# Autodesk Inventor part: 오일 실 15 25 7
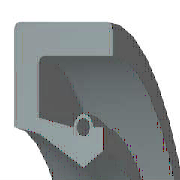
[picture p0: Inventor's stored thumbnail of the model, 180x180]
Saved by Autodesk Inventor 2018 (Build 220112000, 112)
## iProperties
IsCustomPart: 1
Created: 2012-02
Part Number: 오일 실 15 25 7
Material: 고무
Description: 오일 실 - 스프링 장착, 금속 케이스 SM
Document SubType Name: Modeling
Standard: JIS B 2402
Designer: mdu-01
Standards Organization: JIS
Language: ko-KR
Size Designation: 15 25 7 A
Categories: <MemberInstance><Categories><Category DisplayName="샤프트 부품" InternalName="7f7aeb1f-a693-4053-b835-cee3144e0d98" Mnemonic="SHFT"><Category DisplayName="실링" Intern
Density: 0.93 g/cm^3
Appearance: Rubber-Black
Author: mdu-01
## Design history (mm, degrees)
body "Solid1"
revolve "회전1" stored, may be unused: angle "d33" = 360 deg
fillet "모깎기1" dims "d34" = 0.35 (= 0.05 x b)
chamfer "모따기1" distance "d35" = 0.7 (= 0.1 x b); stored, may be unused: second distance "d36" = 0.35 (= 0.05 x b), angle "d41" = 45 deg
sketch "스케치2"
  geometry: L1 (8.714, -5.158)-(9.184, -7); L2 (8.214, -4.55)-(8.714, -5.158); L3 (7.5, -1.75)-(8.214, -4.55); L4 (8.167, -0.875)-(7.5, -1.75); L5 (9.284, -0.875)-(8.167, -0.875); L6 (9.284, -1.575)-(9.284, -0.875); L7 (9.284, -5.25)-(9.284, -2.975); L8 (10.5, -5.25)-(9.284, -5.25); L9 (11.5, -1.75)-(10.5, -5.25); L10 (11.5, 0)-(11.5, -1.75); L11 (12.5, 0)-(11.5, 0); L12 (12.5, -7)-(12.5, 0); L13 (9.184, -7)-(12.5, -7); L14 (0, -9.6)-(0, 1.6) reference; L15 (28, 0)-(14, 0) reference; A1 r 0.7 centre (9.284, -2.275) between (9.284, -2.975) and (9.284, -1.575)
  constraints: 26 end point, 4 horizontal, 4 vertical, 2 point on circle, 1 centre point, 1 collinear, 1 parallel
  dimensions: "d2" = 7 distance of L12.start L11.start (= b); "d4" = 0.875 vertical distance of L10.start L5.start (= 0.125 x b); "d6" = 1 distance of L11.start L10.start (= 0.1 x dd - 0.1 x Diam); "d8" = 1.75 distance of L10.start L9.start (= 0.25 x b); "d10" = 1.75 vertical distance of L8.start L1.end (= 0.25 x b); "d12" = 1 horizontal distance of L9.start L8.start (= 0.1 x dd - 0.1 x Diam); "d14" = 0.7 radius of A1 (= 0.1 x b); "d16" = 0 horizontal distance of A1.centre L7.end; "d18" = 0.7 distance of L6.start L5.start (= 0.1 x b); "d20" = 0.66667 horizontal distance of L4.start L3.start (= 0.0666667 x dd - 0.0666667 x Diam); "d22" = 0.1 horizontal distance of L7.start L1.end (= 0.01 x dd - 0.01 x Diam); "d24" = 0.875 vertical distance of L4.start L3.start (= 0.125 x b); "d26" = 2.8 vertical distance of L3.start L2.start (= 0.4 x b); "d28" = 0.71429 horizontal distance of L3.start L2.start (= 0.0714286 x dd - 0.0714286 x Diam); "d30" = 1.84211 vertical distance of L1.start L1.end (= 0.263158 x b); "d32" = 0.5 horizontal distance of L2.start L1.start (= 0.05 x dd - 0.05 x Diam); "d37" = 0 distance between parallel lines of L15 L11; "d38" = 12.5 distance between parallel lines of L14 L12 (= 0.5 x dd); "d39" = 7.5 distance from line of L14 L3.start (= 0.5 x Diam)
other parameters: "dd" = 25 [user parameter; used in 7 equation terms], "Diam" = 15 [user parameter; used in 7 equation terms], "b" = 7 [user parameter; used in 12 equation terms], "d1" = 8 (derived), "d3" = 1 (derived), "d5" = 2 (derived), "d7" = 2 (derived), "d9" = 2 (derived), "d11" = 2 (derived), "d13" = 0.8 (derived), "d15" = 0 (derived), "d17" = 0.8 (derived), "d19" = 1.33333 (derived), "d21" = 0.2 (derived), "d23" = 1 (derived), "d25" = 3.2 (derived), "d27" = 1.42857 (derived), "d29" = 2.10526 (derived), "d31" = 1 (derived), "d40" = 0
